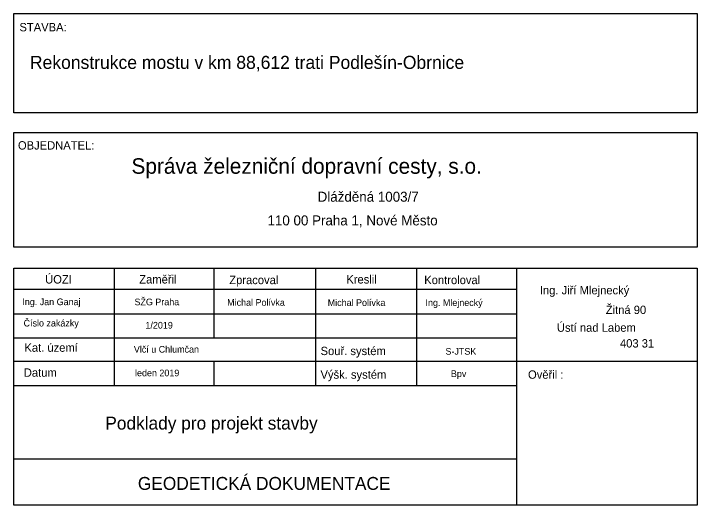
# Model space of a CAD drawing. Extents: x -879530 to -879371, y -1019242 to -1019127.
import ezdxf

# ---------------------------------------------------------------- set-up
doc = ezdxf.new("R2010")
doc.units = 0
doc.layers.add('LEGENDA', color=7, linetype='Continuous')
doc.layers.add('tabulka', color=7, linetype='Continuous')

msp = doc.modelspace()

# ---------------------------------------------------------------- linework, layer by layer
at = {"layer": 'tabulka'}
for p, q in [((-879530.09, -1019186.45), (-879371.44, -1019186.45)), ((-879506.8, -1019186.45), (-879506.8, -1019213.77)), ((-879483.66, -1019186.45), (-879483.66, -1019202.65)), ((-879460.06, -1019186.45), (-879460.06, -1019213.77)), ((-879436.61, -1019186.45), (-879436.61, -1019213.77)), ((-879413.31, -1019241.58), (-879413.31, -1019186.45)), ((-879530.09, -1019191.36), (-879413.31, -1019191.36)), ((-879530.09, -1019197.07), (-879413.31, -1019197.07)), ((-879530.09, -1019202.65), (-879413.31, -1019202.65)), ((-879530.09, -1019208.07), (-879371.44, -1019208.07)), ((-879483.66, -1019208.07), (-879483.66, -1019213.77)), ((-879530.09, -1019213.77), (-879413.31, -1019213.77)), ((-879530.09, -1019230.76), (-879413.31, -1019230.76))]:
    msp.add_line(p, q, dxfattribs=at)
for points in [[(-879530.09, -1019127.36), (-879371.44, -1019127.36), (-879371.44, -1019150.43), (-879530.09, -1019150.43)], [(-879530.09, -1019154.95), (-879371.44, -1019154.95), (-879371.44, -1019181.64), (-879530.09, -1019181.64)]]:
    msp.add_lwpolyline(points, close=True, dxfattribs=at)
msp.add_lwpolyline([(-879371.44, -1019186.45), (-879371.44, -1019241.58), (-879530.09, -1019241.58), (-879530.09, -1019186.45)], dxfattribs=at)

# ---------------------------------------------------------------- texts
at = {"layer": 'LEGENDA'}
msp.add_text('Rekonstrukce mostu v km 88,612 trati Podlešín-Obrnice', height=3.04, dxfattribs=at).set_placement((-879526.32, -1019140.2))
at = {"layer": 'tabulka'}
for s, height, p in [('STAVBA:', 1.94, (-879528.75, -1019131.47)), ('OBJEDNATEL:', 1.94, (-879529.1, -1019158.93)), ('Správa železniční dopravní cesty, s.o.', 3.61, (-879502.75, -1019164.56)), ('Dlážděná 1003/7', 2.32, (-879459.55, -1019171.05)), ('110 00 Praha 1, Nové Město', 2.32, (-879471.19, -1019176.55)), ('ÚOZI', 1.94, (-879522.79, -1019190.05)), ('Zaměřil', 1.94, (-879500.95, -1019190.05)), ('Zpracoval', 1.94, (-879480.06, -1019190.2)), ('Kreslil', 1.94, (-879452.9, -1019190.05)), ('Kontroloval', 1.94, (-879434.81, -1019190.2)), ('Ing. Jiří Mlejnecký', 1.94, (-879407.98, -1019192.57)), ('Ing. Jan Ganaj', 1.552, (-879528.08, -1019195.08)), ('SŽG Praha', 1.552, (-879502.06, -1019195.11)), ('Michal Polívka', 1.552, (-879480.54, -1019195.23)), ('Michal Polívka', 1.552, (-879457.21, -1019195.27)), ('Ing. Mlejnecký', 1.552, (-879434.52, -1019195.27)), ('Žitná 90', 1.94, (-879392.68, -1019197.14)), ('Číslo zakázky', 1.552, (-879527.79, -1019200.03)), ('1/2019', 1.552, (-879499.51, -1019200.52)), ('Ústí nad Labem', 1.94, (-879404.02, -1019201.26)), ('403 31', 1.94, (-879389.39, -1019204.92)), ('Kat. území', 1.94, (-879527.6, -1019205.91)), ('Vlčí u Chlumčan', 1.552, (-879502.2, -1019206.11)), ('Souř. systém', 1.94, (-879458.87, -1019206.68)), ('S-JTSK', 1.552, (-879429.88, -1019206.59)), ('Datum', 1.94, (-879527.74, -1019211.71)), ('leden 2019', 1.552, (-879501.93, -1019211.6)), ('Výšk. systém', 1.94, (-879458.89, -1019212.17)), ('Bpv', 1.552, (-879428.62, -1019211.78)), ('Ověřil :', 1.94, (-879410.72, -1019212.17)), ('Podklady pro projekt stavby', 3, (-879508.83, -1019223.98)), ('GEODETICKÁ DOKUMENTACE ', 3, (-879501.27, -1019237.99))]:
    msp.add_text(s, height=height, dxfattribs=at).set_placement(p)

doc.saveas('drawing.dxf')
